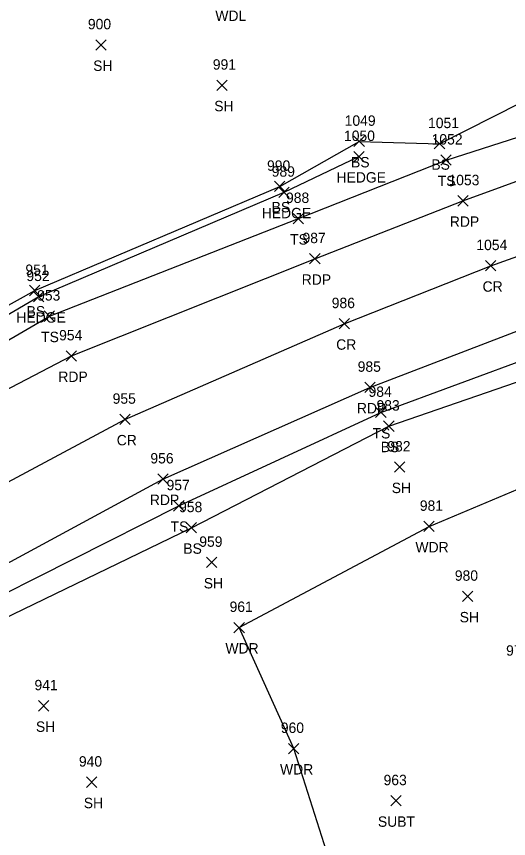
# Model space of a CAD drawing. Extents: x 1586965 to 1590952, y 716317 to 720029.
# Drawn here: x 1587407.7 to 1587502.3, y 719678.7 to 719836.9 of the extents above; entities that cross this region are included whole.
import ezdxf

# ---------------------------------------------------------------- set-up
doc = ezdxf.new("R2010")
doc.units = 0
for name, color, linetype in [('L_A', 7, 'Continuous'), ('L_I', 7, 'Continuous'), ('L_TIC', 7, 'Continuous'), ('LAHR', 7, 'Continuous'), ('LAWA', 7, 'Continuous'), ('LELB', 7, 'Continuous'), ('P_A', 7, 'Continuous'), ('P_I', 7, 'Continuous'), ('P_TIC', 7, 'Continuous'), ('PET', 7, 'Continuous'), ('PRC', 7, 'Continuous'), ('U_A', 7, 'Continuous'), ('U_I', 7, 'Continuous'), ('U_TIC', 7, 'Continuous')]:
    doc.layers.add(name, color=color, linetype=linetype)

msp = doc.modelspace()

# ---------------------------------------------------------------- linework, layer by layer
at = {"layer": 'L_TIC'}
for points in [[(1587422.98, 719830.39), (1587424.98, 719832.39)], [(1587424.98, 719830.39), (1587422.98, 719832.39)], [(1587446.26, 719822.63), (1587448.26, 719824.63)], [(1587448.26, 719822.63), (1587446.26, 719824.63)], [(1587472.61, 719811.83), (1587474.61, 719813.83)], [(1587474.61, 719811.83), (1587472.61, 719813.83)], [(1587488.06, 719811.38), (1587490.06, 719813.38)], [(1587490.06, 719811.38), (1587488.06, 719813.38)], [(1587472.56, 719808.91), (1587474.56, 719810.91)], [(1587474.56, 719808.91), (1587472.56, 719810.91)], [(1587489.32, 719808.23), (1587491.32, 719810.23)], [(1587491.32, 719808.23), (1587489.32, 719810.23)], [(1587457.35, 719803.18), (1587459.35, 719805.18)], [(1587459.35, 719803.18), (1587457.35, 719805.18)], [(1587458.17, 719802.04), (1587460.17, 719804.04)], [(1587460.17, 719802.04), (1587458.17, 719804.04)], [(1587460.92, 719796.99), (1587462.92, 719798.99)], [(1587462.92, 719796.99), (1587460.92, 719798.99)], [(1587410.23, 719783.15), (1587412.23, 719785.15)], [(1587412.23, 719783.15), (1587410.23, 719785.15)], [(1587410.99, 719781.97), (1587412.99, 719783.97)], [(1587412.99, 719781.97), (1587410.99, 719783.97)], [(1587413.05, 719778.22), (1587415.05, 719780.22)], [(1587415.05, 719778.22), (1587413.05, 719780.22)], [(1587476.78, 719759.7), (1587478.78, 719761.7)], [(1587478.78, 719759.7), (1587476.78, 719761.7)], [(1587478.32, 719757.06), (1587480.32, 719759.06)], [(1587480.32, 719757.06), (1587478.32, 719759.06)], [(1587480.39, 719749.19), (1587482.39, 719751.19)], [(1587482.39, 719749.19), (1587480.39, 719751.19)], [(1587437.94, 719741.74), (1587439.94, 719743.74)], [(1587439.94, 719741.74), (1587437.94, 719743.74)], [(1587440.36, 719737.52), (1587442.36, 719739.52)], [(1587442.36, 719737.52), (1587440.36, 719739.52)], [(1587486.07, 719737.78), (1587488.07, 719739.78)], [(1587488.07, 719737.78), (1587486.07, 719739.78)], [(1587444.24, 719730.86), (1587446.24, 719732.86)], [(1587446.24, 719730.86), (1587444.24, 719732.86)], [(1587493.46, 719724.33), (1587495.46, 719726.33)], [(1587495.46, 719724.33), (1587493.46, 719726.33)], [(1587449.54, 719718.33), (1587451.54, 719720.33)], [(1587451.54, 719718.33), (1587449.54, 719720.33)], [(1587411.97, 719703.27), (1587413.97, 719705.27)], [(1587413.97, 719703.27), (1587411.97, 719705.27)], [(1587460.04, 719695.06), (1587462.04, 719697.06)], [(1587462.04, 719695.06), (1587460.04, 719697.06)], [(1587421.17, 719688.59), (1587423.17, 719690.59)], [(1587423.17, 719688.59), (1587421.17, 719690.59)]]:
    msp.add_lwpolyline(points, dxfattribs=at)
at = {"layer": 'LAHR'}
msp.add_lwpolyline([(1587348.6, 719747.64), (1587376.46, 719762.15), (1587411.99, 719782.97), (1587459.17, 719803.04), (1587473.56, 719809.91)], dxfattribs=at)
at = {"layer": 'LAWA'}
msp.add_lwpolyline([(1587401.27, 719626.51), (1587435.01, 719634.6), (1587448.14, 719647.08), (1587470.91, 719665.01), (1587461.04, 719696.06), (1587450.54, 719719.33), (1587487.07, 719738.78), (1587518.72, 719752.12), (1587550.39, 719765.58), (1587600.64, 719780.12), (1587625.51, 719792.71), (1587653.44, 719805), (1587664.38, 719814.47), (1587690.31, 719819.83), (1587699.11, 719820.97), (1587725.45, 719821.57), (1587738.15, 719822.66), (1587747.89, 719823.3), (1587771.26, 719823.5), (1587792.66, 719819.32), (1587813.67, 719812.11)], dxfattribs=at)
at = {"layer": 'LELB'}
for points in [[(1587348.34, 719750.32), (1587376.14, 719764.57), (1587411.23, 719784.15), (1587458.35, 719804.18), (1587473.61, 719812.83), (1587489.06, 719812.38), (1587530.46, 719833.31), (1587544.39, 719838.73), (1587578.28, 719845.78), (1587610.35, 719855.43), (1587636.65, 719869.8), (1587651.78, 719871.98), (1587673.75, 719879.3), (1587684.98, 719885.25), (1587696.5, 719901.07), (1587712.21, 719917.3), (1587727.23, 719932.21), (1587743.8, 719944.38), (1587761.72, 719949.74)], [(1587348.34, 719750.32), (1587376.14, 719764.57), (1587411.23, 719784.15), (1587458.35, 719804.18), (1587473.61, 719812.83), (1587489.06, 719812.38), (1587530.46, 719833.31), (1587544.39, 719838.73), (1587578.28, 719845.78), (1587610.35, 719855.43), (1587636.65, 719869.8), (1587651.78, 719871.98), (1587673.75, 719879.3), (1587684.98, 719885.25), (1587696.5, 719901.07), (1587712.21, 719917.3), (1587727.23, 719932.21), (1587743.8, 719944.38), (1587761.72, 719949.74)], [(1587377.37, 719757.84), (1587414.05, 719779.22), (1587461.92, 719797.99), (1587490.32, 719809.23), (1587530.45, 719822.09), (1587580.58, 719835.52), (1587609.69, 719843.39), (1587653.83, 719853.5), (1587683.02, 719862.16), (1587697.57, 719874.31), (1587709.76, 719884.81), (1587725.71, 719899.33), (1587733.52, 719907.93), (1587757.13, 719931.09), (1587771.49, 719945.87)], [(1587377.37, 719757.84), (1587414.05, 719779.22), (1587461.92, 719797.99), (1587490.32, 719809.23), (1587530.45, 719822.09), (1587580.58, 719835.52), (1587609.69, 719843.39), (1587653.83, 719853.5), (1587683.02, 719862.16), (1587697.57, 719874.31), (1587709.76, 719884.81), (1587725.71, 719899.33), (1587733.52, 719907.93), (1587757.13, 719931.09), (1587771.49, 719945.87)], [(1587398.24, 719722.21), (1587438.94, 719742.74), (1587477.78, 719760.7), (1587507.65, 719771.73), (1587544.05, 719780.86), (1587591.35, 719799.64), (1587619.1, 719805.45), (1587663.03, 719817.76), (1587689.98, 719823.61), (1587724.39, 719827.01), (1587769.54, 719828.25), (1587817.81, 719818.92)], [(1587398.24, 719722.21), (1587438.94, 719742.74), (1587477.78, 719760.7), (1587507.65, 719771.73), (1587544.05, 719780.86), (1587591.35, 719799.64), (1587619.1, 719805.45), (1587663.03, 719817.76), (1587689.98, 719823.61), (1587724.39, 719827.01), (1587769.54, 719828.25), (1587817.81, 719818.92)], [(1587400.93, 719718.94), (1587441.36, 719738.52), (1587479.32, 719758.06), (1587509.44, 719768.45), (1587545.37, 719776.35), (1587593.67, 719793.11), (1587606.58, 719796.72), (1587619.17, 719803.04), (1587621.11, 719802.76), (1587621.24, 719800.99), (1587625.17, 719804.67), (1587651.6, 719808.85)], [(1587400.93, 719718.94), (1587441.36, 719738.52), (1587479.32, 719758.06), (1587509.44, 719768.45), (1587545.37, 719776.35), (1587593.67, 719793.11), (1587606.58, 719796.72), (1587619.17, 719803.04), (1587621.11, 719802.76), (1587621.24, 719800.99), (1587625.17, 719804.67), (1587651.6, 719808.85)]]:
    msp.add_lwpolyline(points, dxfattribs=at)
at = {"layer": 'P_TIC'}
for points in [[(1587492.56, 719800.4), (1587494.56, 719802.4)], [(1587494.56, 719800.4), (1587492.56, 719802.4)], [(1587464.09, 719789.26), (1587466.09, 719791.26)], [(1587466.09, 719789.26), (1587464.09, 719791.26)], [(1587497.92, 719787.92), (1587499.92, 719789.92)], [(1587499.92, 719787.92), (1587497.92, 719789.92)], [(1587469.76, 719776.76), (1587471.76, 719778.76)], [(1587471.76, 719776.76), (1587469.76, 719778.76)], [(1587417.28, 719770.56), (1587419.28, 719772.56)], [(1587419.28, 719770.56), (1587417.28, 719772.56)], [(1587474.69, 719764.52), (1587476.69, 719766.52)], [(1587476.69, 719764.52), (1587474.69, 719766.52)], [(1587427.57, 719758.37), (1587429.57, 719760.37)], [(1587429.57, 719758.37), (1587427.57, 719760.37)], [(1587434.88, 719746.89), (1587436.88, 719748.89)], [(1587436.88, 719746.89), (1587434.88, 719748.89)]]:
    msp.add_lwpolyline(points, dxfattribs=at)
at = {"layer": 'PET'}
for points in [[(1587380.68, 719751.95), (1587418.28, 719771.56), (1587465.09, 719790.26), (1587493.56, 719801.4), (1587532.06, 719815.42), (1587581.77, 719830.86), (1587610.56, 719839.15), (1587655.26, 719849.11), (1587685.91, 719854.02), (1587717.2, 719859.97), (1587741.36, 719862.44), (1587760.59, 719863.49), (1587776.56, 719860.57), (1587795.98, 719858.74), (1587820.3, 719853.13)], [(1587395.82, 719726.18), (1587435.88, 719747.89), (1587475.69, 719765.52), (1587505.58, 719777), (1587541.23, 719789.76), (1587588.97, 719805.25), (1587616.65, 719812.47), (1587661.21, 719823.51), (1587689.19, 719828.4), (1587723.88, 719833.21), (1587769.59, 719834.05), (1587819.16, 719826.14)]]:
    msp.add_lwpolyline(points, dxfattribs=at)
at = {"layer": 'PRC'}
msp.add_lwpolyline([(1587388.91, 719738.13), (1587428.57, 719759.37), (1587470.76, 719777.76), (1587498.92, 719788.92), (1587537.38, 719802.71), (1587585.33, 719817.72), (1587613.69, 719825.22), (1587658.7, 719835.7), (1587687.69, 719841.3), (1587721.6, 719845.66), (1587770.57, 719846.88), (1587822.37, 719838.71)], dxfattribs=at)
msp.add_lwpolyline([(1587388.91, 719738.13), (1587428.57, 719759.37), (1587470.76, 719777.76), (1587498.92, 719788.92), (1587537.38, 719802.71), (1587585.33, 719817.72), (1587613.69, 719825.22), (1587658.7, 719835.7), (1587687.69, 719841.3), (1587721.6, 719845.66), (1587770.57, 719846.88), (1587822.37, 719838.71)], dxfattribs=at)
at = {"layer": 'U_TIC'}
for points in [[(1587479.72, 719685.01), (1587481.72, 719687.01)], [(1587481.72, 719685.01), (1587479.72, 719687.01)]]:
    msp.add_lwpolyline(points, dxfattribs=at)

# ---------------------------------------------------------------- texts
at = {"layer": 'L_A'}
for s, p in [('WDL', (1587445.96, 719835.99)), ('SH', (1587422.47, 719826.39)), ('SH', (1587445.75, 719818.63)), ('BS', (1587472.05, 719807.83)), ('BS', (1587487.5, 719807.38)), ('HEDGE', (1587469.26, 719804.91)), ('TS', (1587488.73, 719804.23)), ('BS', (1587456.79, 719799.18)), ('HEDGE', (1587454.88, 719798.04)), ('TS', (1587460.33, 719792.99)), ('BS', (1587409.67, 719779.15)), ('HEDGE', (1587407.69, 719777.97)), ('TS', (1587412.46, 719774.22)), ('TS', (1587476.19, 719755.7)), ('BS', (1587477.76, 719753.06)), ('SH', (1587479.88, 719745.19)), ('TS', (1587437.35, 719737.74)), ('BS', (1587439.8, 719733.52)), ('WDR', (1587484.44, 719733.78)), ('SH', (1587443.73, 719726.86)), ('SH', (1587492.95, 719720.33)), ('WDR', (1587447.9, 719714.33)), ('SH', (1587411.46, 719699.27)), ('WDR', (1587458.4, 719691.06)), ('SH', (1587420.66, 719684.59))]:
    msp.add_text(s, height=2, dxfattribs=at).set_placement(p)
at = {"layer": 'L_I'}
for s, p in [('900', (1587421.45, 719834.39)), ('991', (1587445.47, 719826.63)), ('1049', (1587470.83, 719815.83)), ('1051', (1587486.86, 719815.38)), ('1050', (1587470.7, 719812.91)), ('1052', (1587487.55, 719812.23)), ('990', (1587455.9, 719807.18)), ('989', (1587456.8, 719806.04)), ('988', (1587459.55, 719800.99)), ('951', (1587409.44, 719787.15)), ('952', (1587409.63, 719785.97)), ('953', (1587411.69, 719782.22)), ('984', (1587475.42, 719763.7)), ('983', (1587476.95, 719761.06)), ('982', (1587479.03, 719753.19)), ('957', (1587436.58, 719745.74)), ('981', (1587485.28, 719741.78)), ('958', (1587438.99, 719741.52)), ('959', (1587442.87, 719734.86)), ('980', (1587492.01, 719728.33)), ('961', (1587448.7, 719722.33)), ('979', (1587501.87, 719713.92)), ('941', (1587411.18, 719707.27)), ('960', (1587458.55, 719699.06)), ('940', (1587419.72, 719692.59))]:
    msp.add_text(s, height=2, dxfattribs=at).set_placement(p)
at = {"layer": 'P_A'}
for s, p in [('RDP', (1587491.05, 719796.4)), ('RDP', (1587462.57, 719785.26)), ('CR', (1587497.35, 719783.92)), ('CR', (1587469.2, 719772.76)), ('RDP', (1587415.77, 719766.56)), ('RDP', (1587473.18, 719760.52)), ('CR', (1587427, 719754.37)), ('RDP', (1587433.37, 719742.89))]:
    msp.add_text(s, height=2, dxfattribs=at).set_placement(p)
at = {"layer": 'P_I'}
for s, p in [('1053', (1587490.79, 719804.4)), ('987', (1587462.72, 719793.26)), ('1054', (1587496.15, 719791.92)), ('986', (1587468.34, 719780.76)), ('954', (1587415.92, 719774.56)), ('985', (1587473.33, 719768.52)), ('955', (1587426.21, 719762.37)), ('956', (1587433.47, 719750.89))]:
    msp.add_text(s, height=2, dxfattribs=at).set_placement(p)
at = {"layer": 'U_A'}
msp.add_text('SUBT', height=2, dxfattribs=at).set_placement((1587477.22, 719681.01))
at = {"layer": 'U_I'}
msp.add_text('963', height=2, dxfattribs=at).set_placement((1587478.31, 719689.01))

doc.saveas('drawing.dxf')
